(* Logix 5000 project; controller Test vendor 1 type 14 code 92 rev 33.11; software revision 33.03 *)

TASK MainTask (continuous, watchdog 500 ms) : MainProgram

MODULES
   Local : vendor 1 type 14 code 92 (ICP 0, rev 33.11)
      IN : vendor 1 type 7 code 1 (ICP 3, rev 3.2, Input RPI 20 ms)
      O : vendor 1 type 7 code 15 (ICP 2, rev 3.2, Output RPI 20 ms)
      Ethernet : 1756-ENBT (ICP 1, Ethernet 192.168.0.98, rev 6.4)
         IOLM1 : DXM (Ethernet 192.168.0.1, rev 2.22, StandardDataDriven RPI 20 ms)
              IOLM1:I.Data[184].0   // Output State
              IOLM1:I.Data[184].1   // Health Alarm State
END_MODULES

TYPE Banner_B25_Configuration_v4 :
STRUCT
   Sensor_Lockout : SINT;   // 0=Unlocked, 1=Locked
   Sensitivity : SINT;   // 0=Low, 1=Standard, 2=High
   Pin2_Function : SINT;   // 0=Disabled, 1=Remote Teach, 2=Detection Output, 3=Complementary Output, 4=NC Health, 5=NO Health
   Pin2_Pin4_Polarity : SINT;   // 0=NPN, 1=PNP, 2=Push Pull
   Output_Logic : SINT;   // 0=LO, 1= DO
   Output_Delay_Mode : SINT;   // 0=No Delay, 1=On/Off Delay
   Output_On_Delay : DINT;
   Output_Off_Delay : DINT;
   Dynamic_Teach_Timeout_Mode : SINT;   // 0=Cancel Teach, 1=Stop Teach
   Dynamic_Teach_Timeout_Duration : DINT;
   Health_Alarm_Threshold : SINT;
   Display_Disable : SINT;   // 0=Enabled, 1=Disabled
END_STRUCT
END_TYPE

TYPE Banner_B25_PDI_v4 :   // Process Data for a B25. This will include event information.
STRUCT
   Output_State : SINT;   // 0 = Inactive, 1 = Active
   Marginal_Signal : SINT;   // 0 = Normal, 1 = Marginal
END_STRUCT
END_TYPE

TYPE Banner_B25_RD_v4 :   // UDT that stores the Read Data for a B25.
STRUCT
   Direct : Banner_Direct_Parameters_v4;
   Serial_Number : STRING;
   Teach_State : SINT;   // 0=Idle, 1=SP1 Success, 2=SP2 Succes, 3=SP1 SP2 Success, 4 = Wait for Command, 5 = Busy, 7 = Error.
   Status : Banner_B25_Status_v4;
   All_Time_Run_Time_Counter : DINT;   // 0 to 2 Billion. 1/4 hr increments.
END_STRUCT
END_TYPE

TYPE Banner_B25_Status_v4 :
STRUCT
   Output_State : SINT;   // 0=Inactive, 1=Active
   Signal_Level : SINT;   // Signal Level - Switchpoit is at 50%, Taught Signal is at 100%
   Temperature : DINT;   // Internal Temperature
   Last_Taught_Temperature : DINT;   // Internal Temperature the last time device was taught
   Quality_of_Teach : SINT;   // 0=Not Taught, 1=Good, 2=Bad
   Health_Alarm_State : SINT;   // 0=No Alarm, 1= Alarm
   Quality_of_Health : INT;
END_STRUCT
END_TYPE

TYPE Banner_B25_v4 :   // All of the parameters for a B25.
STRUCT
   Initial_Global_Read : BOOL;   // Determines if all of the IO-Link data has been read into the PLC yet
   Command : INT;   // Value placed in here will activate a read or write to a specifc IO-Link Index
   Read : Banner_B25_RD_v4;   // Read Only Data
   Write : Banner_B25_WD_v4;   // Write Data
   Reset : BOOL;   // Resets AOI. This will force a complete parameter read of the sensor.
END_STRUCT
END_TYPE

TYPE Banner_B25_WD_v4 :   // UDT that stores the Write Data for a B25.
STRUCT
   System_Command : INT;   // See IODD file for list of commands that can be activated via the System Command interface
   Parameter_Access_Lock : SINT;   // Write access to all parameters is prohibited while value is 1. Only this parameter can be adjusted when value is 1.
   Data_Storage_Lock : SINT;   // Automatic data storage is disabled when this value is equal to 1. Read access is not affected.
   Local_Parameterization_Lock : SINT;   // Parameterization via local control elements on device is disabled.
   Local_User_Interface_Lock : SINT;   // Operation of local user interface is disabled.
   Configuration : Banner_B25_Configuration_v4;
   Resettable_Run_Time_Counter : DINT;   // 0 to 2 Billion. 1/4 hr increments.
   All_Time_Run_Time_Event_Time : DINT;   // 0 to 2 Billion. 1/4 hr increments.
   Resettable_Run_Time_Event_Time_Counter : DINT;   // 0 to 2 Billion. 1/4 hr increments.
END_STRUCT
END_TYPE

TYPE Banner_Direct_Parameters_v4 :
STRUCT
   Master_Cycle_Time : INT;
   Min_Cycle_Time : INT;
   M_Sequence_Capability : INT;
   IO_Link_Version_ID : INT;
   Process_Data_Input_Length : INT;
   Process_Data_Output_Length : INT;
   Combined_Vendor_ID : DINT;   // IO-Link Vendor ID
   Vendor_ID1 : INT;
   Vendor_ID2 : INT;
   Combined_Device_ID : DINT;   // IO-Link Device ID
   Device_ID1 : INT;
   Device_ID2 : INT;
   Device_ID3 : INT;
END_STRUCT
END_TYPE

TYPE Banner_IOL_Port_v4 :   // UDT that has all of the data items necessary to communicate with a specific Port on a IO-Link Master
STRUCT
   Port_Controlled : INT;   // Each bit represents a port on an IO-Link Master. Set to 1 to tell AOI to control that port.
   Port_Activate : INT;   // Each bit represents a port on an IO-Link Master. When ON that port will process any commands in queue.
   Port_Read : INT;   // Each bit represents a port on an IO-Link Master. Used to determine when device AOI has requested a Read command.
   Port_Write : INT;   // Each bit represents a port on an IO-Link Master. Used to determine when device AOI has requested a Write command.
   Port_RW_Complete : INT;   // Each bit represents a port on an IO-Link Master. Tells device AOI that Read or Write request has been completed.
   Port_Device_Read : INT;
   Data_Transfer : SINT[190];   // Array to transfer data from IO-Master to device AOIs.
END_STRUCT
END_TYPE

TYPE Banner_IOLM_EL_v4 :   // Error Log for Messages to IOLM.
STRUCT
   RW : SINT;   // 0 = Read, 1 = Write.
   Port : SINT;   // Port number that generated error.
   Index : INT;   // IO-Link Index for generated error.
END_STRUCT
END_TYPE

TYPE Banner_IOLM_v4 :   // UDT to control IO-Link Masters.
STRUCT
   Message_Source_Data : SINT[190];
   Message_Destination_Data : SINT[190];
   Error_Log : Banner_IOLM_EL_v4[10];
   Error_Write_Retry : BOOL;
   Num_Error_MSGS : DINT;
   IO_Link_Master_Busy : BOOL;   // 0 = While waiting for a command, 1 = Processing command
   AOI_Reset : BOOL;
   Port_Data : Banner_IOL_Port_v4;   // All of the necessary data to work with the various ports of the IO-Link Master.
   Halt_Operation : BOOL;   // When parameter is 1 the AOI is halted as next available time frame.
   AOI_Halted : BOOL;   // AOI is in standby mode until Halt Operation tag is set back to 0.
END_STRUCT
END_TYPE

ADD_ON_INSTRUCTION Banner_B25_Param_v4   (* revision 4.0, vendor Banner Engineering *)
// AOI to read and write parameter data to an IO-Link B25.
VAR_IN_OUT
   B25 : Banner_B25_v4; {required}
   Port_Data : Banner_IOL_Port_v4; {required}
END_VAR
VAR_INPUT
   Port : DINT; {required}
END_VAR
VAR
   Local_Control : DINT; {access None}
   Global_Read_Command_Value : INT; {access None}
   Global_Write_Command_Value : INT; {access None}
   Command_Being_Processed : BOOL; {access None}
   Update_Archive : BOOL; {access None}
   Index_Write_Inprocess : INT; {access None}
   Index_Write_Control : INT; {access None}
   Inprocess_Index : DINT; {access None}
END_VAR

ROUTINE Logic   (* ladder *)
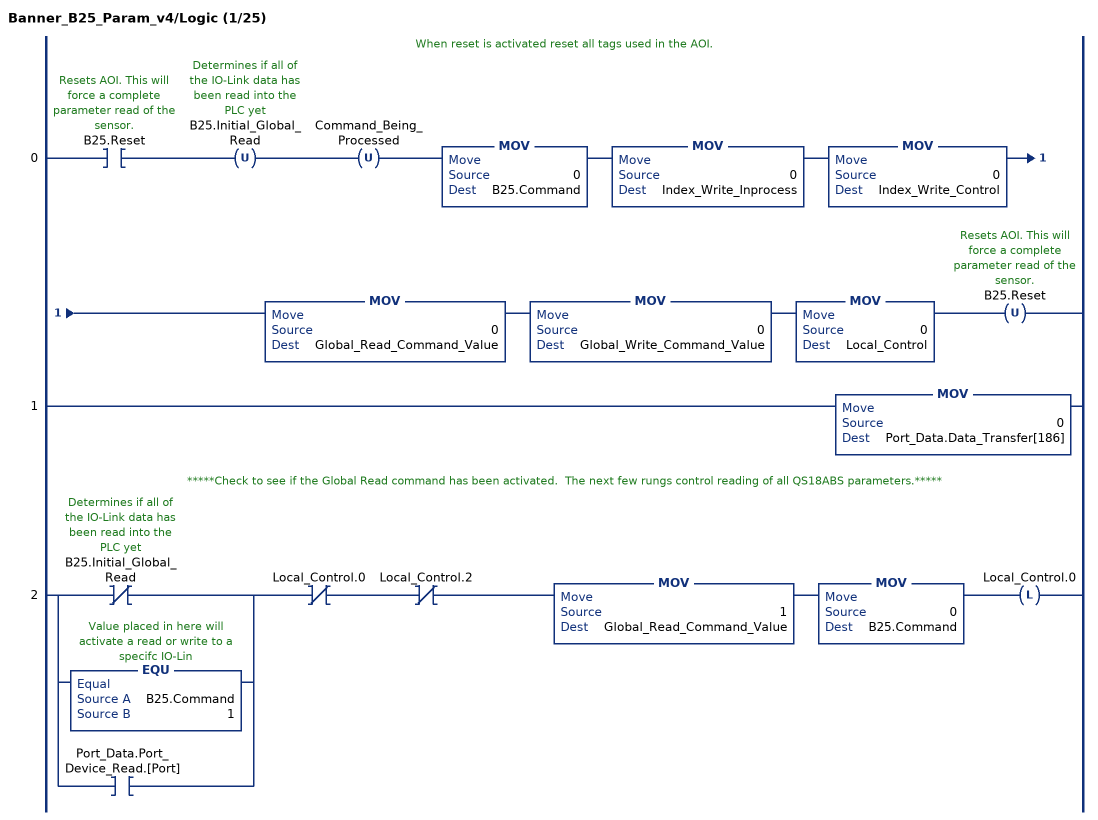
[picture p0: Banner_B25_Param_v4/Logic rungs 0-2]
   // When reset is activated reset all tags used in the AOI.
   0: XIC(B25.Reset)OTU(B25.Initial_Global_Read)OTU(Command_Being_Processed)MOV(0,B25.Command)MOV(0,Index_Write_Inprocess)MOV(0,Index_Write_Control)MOV(0,Global_Read_Command_Value)MOV(0,Global_Write_Command_Value)MOV(0,Local_Control)OTU(B25.Reset);
   1: MOV(0,Port_Data.Data_Transfer[186]);
   // *****Check to see if the Global Read command has been activated.  The next few rungs control reading of all QS18ABS parameters.*****
   2: [XIO(B25.Initial_Global_Read) ,EQU(B25.Command,1) ,XIC(Port_Data.Port_Device_Read.[Port]) ]XIO(Local_Control.0)XIO(Local_Control.2)MOV(1,Global_Read_Command_Value)MOV(0,B25.Command)OTL(Local_Control.0);
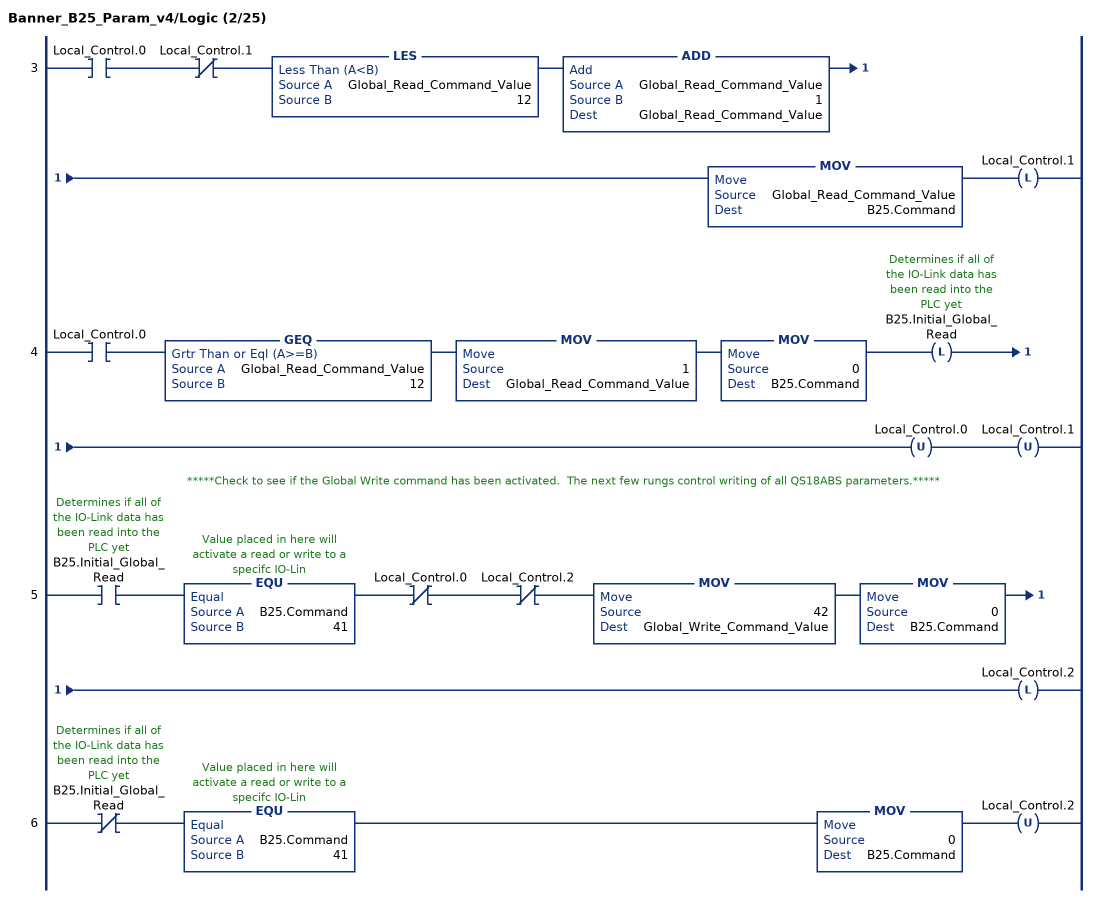
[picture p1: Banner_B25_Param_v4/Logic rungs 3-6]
   3: XIC(Local_Control.0)XIO(Local_Control.1)LES(Global_Read_Command_Value,12)ADD(Global_Read_Command_Value,1,Global_Read_Command_Value)MOV(Global_Read_Command_Value,B25.Command)OTL(Local_Control.1);
   4: XIC(Local_Control.0)GEQ(Global_Read_Command_Value,12)MOV(1,Global_Read_Command_Value)MOV(0,B25.Command)OTL(B25.Initial_Global_Read)OTU(Local_Control.0)OTU(Local_Control.1);
   // *****Check to see if the Global Write command has been activated.  The next few rungs control writing of all QS18ABS parameters.*****
   5: XIC(B25.Initial_Global_Read)EQU(B25.Command,41)XIO(Local_Control.0)XIO(Local_Control.2)MOV(42,Global_Write_Command_Value)MOV(0,B25.Command)OTL(Local_Control.2);
   6: XIO(B25.Initial_Global_Read)EQU(B25.Command,41)MOV(0,B25.Command)OTU(Local_Control.2);
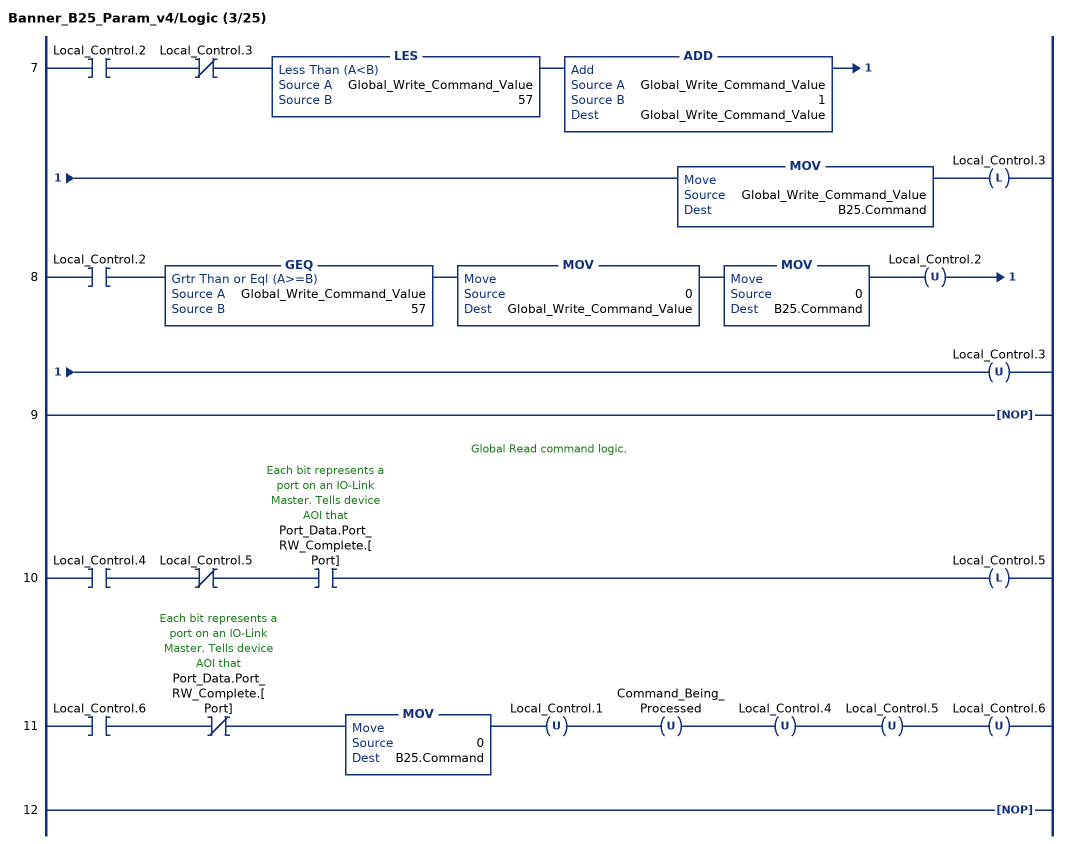
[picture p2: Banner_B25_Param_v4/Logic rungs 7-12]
   7: XIC(Local_Control.2)XIO(Local_Control.3)LES(Global_Write_Command_Value,57)ADD(Global_Write_Command_Value,1,Global_Write_Command_Value)MOV(Global_Write_Command_Value,B25.Command)OTL(Local_Control.3);
   8: XIC(Local_Control.2)GEQ(Global_Write_Command_Value,57)MOV(0,Global_Write_Command_Value)MOV(0,B25.Command)OTU(Local_Control.2)OTU(Local_Control.3);
   9: NOP();
   // Global Read command logic.
   10: XIC(Local_Control.4)XIO(Local_Control.5)XIC(Port_Data.Port_RW_Complete.[Port])OTL(Local_Control.5);
   11: XIC(Local_Control.6)XIO(Port_Data.Port_RW_Complete.[Port])MOV(0,B25.Command)OTU(Local_Control.1)OTU(Command_Being_Processed)OTU(Local_Control.4)OTU(Local_Control.5)OTU(Local_Control.6);
   12: NOP();
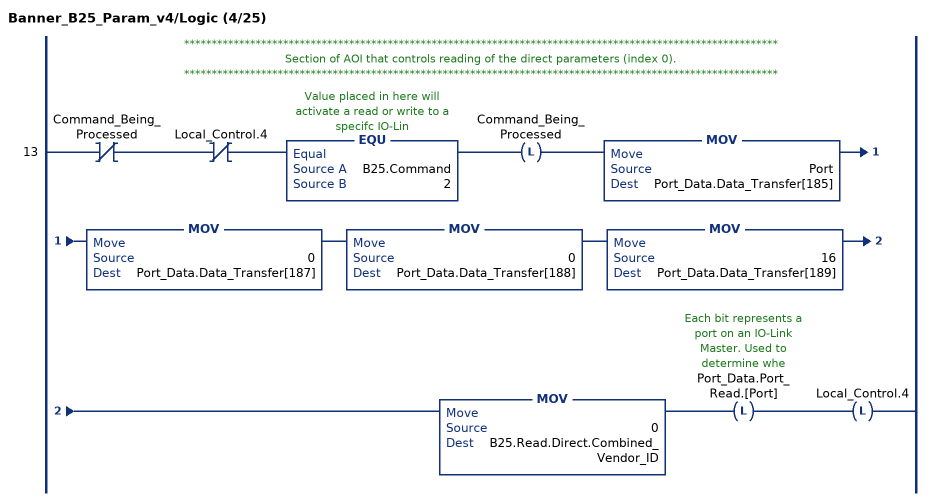
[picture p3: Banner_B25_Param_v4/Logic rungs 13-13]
   // ************************************************************************************************************
   // Section of AOI that controls reading of the direct parameters (index 0).
   // ************************************************************************************************************
   13: XIO(Command_Being_Processed)XIO(Local_Control.4)EQU(B25.Command,2)OTL(Command_Being_Processed)MOV(Port,Port_Data.Data_Transfer[185])MOV(0,Port_Data.Data_Transfer[187])MOV(0,Port_Data.Data_Transfer[188])MOV(16,Port_Data.Data_Transfer[189])MOV(0,B25.Read.Direct.Combined_Vendor_ID)OTL(Port_Data.Port_Read.[Port])OTL(Local_Control.4);
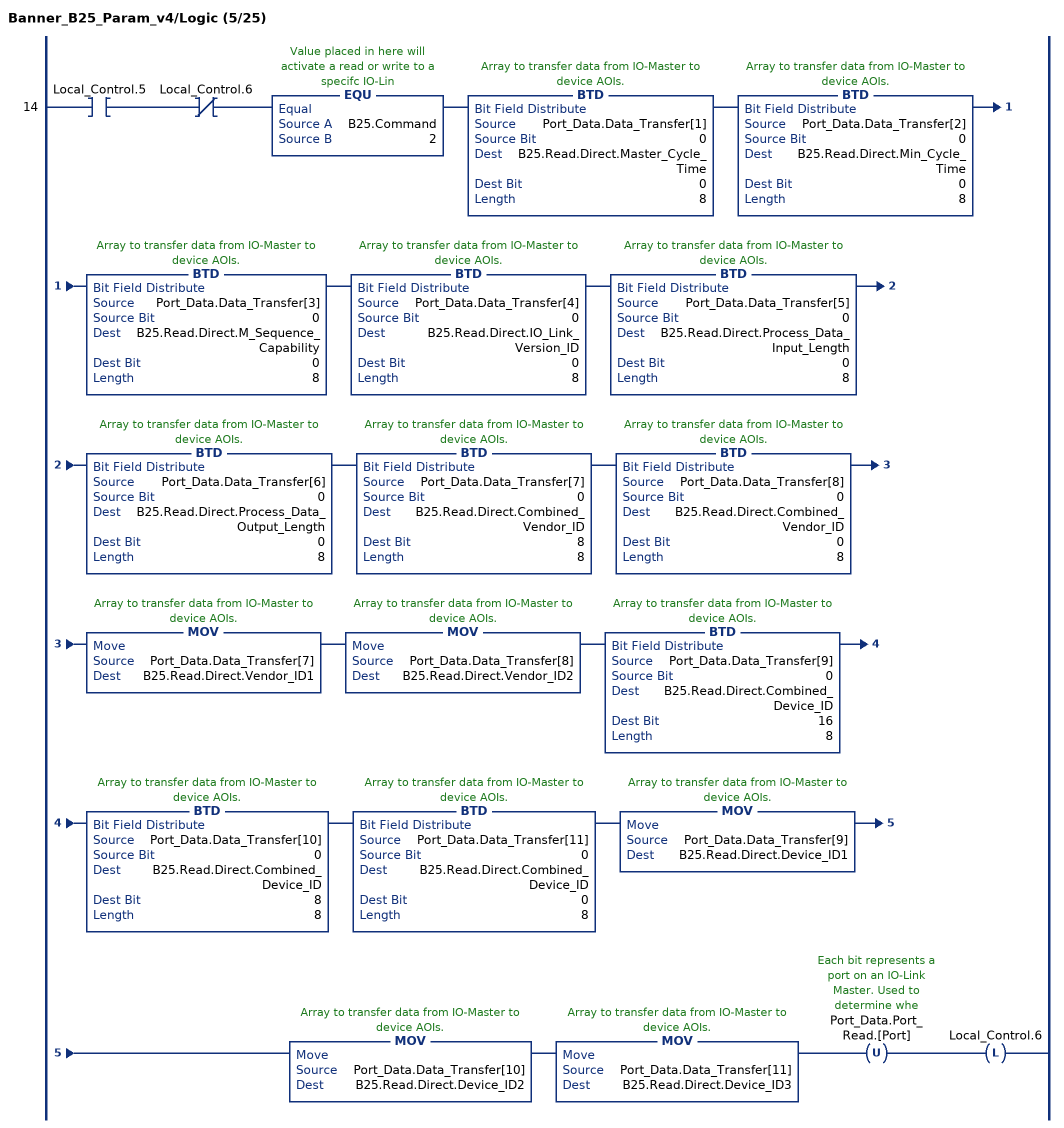
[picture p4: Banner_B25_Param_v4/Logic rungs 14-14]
   14: XIC(Local_Control.5)XIO(Local_Control.6)EQU(B25.Command,2)BTD(Port_Data.Data_Transfer[1],0,B25.Read.Direct.Master_Cycle_Time,0,8)BTD(Port_Data.Data_Transfer[2],0,B25.Read.Direct.Min_Cycle_Time,0,8)BTD(Port_Data.Data_Transfer[3],0,B25.Read.Direct.M_Sequence_Capability,0,8)BTD(Port_Data.Data_Transfer[4],0,B25.Read.Direct.IO_Link_Version_ID,0,8)BTD(Port_Data.Data_Transfer[5],0,B25.Read.Direct.Process_Data_Input_Length,0,8)BTD(Port_Data.Data_Transfer[6],0,B25.Read.Direct.Process_Data_Output_Length,0,8)BTD(Port_Data.Data_Transfer[7],0,B25.Read.Direct.Combined_Vendor_ID,8,8)BTD(Port_Data.Data_Transfer[8],0,B25.Read.Direct.Combined_Vendor_ID,0,8)MOV(Port_Data.Data_Transfer[7],B25.Read.Direct.Vendor_ID1)MOV(Port_Data.Data_Transfer[8],B25.Read.Direct.Vendor_ID2)BTD(Port_Data.Data_Transfer[9],0,B25.Read.Direct.Combined_Device_ID,16,8)BTD(Port_Data.Data_Transfer[10],0,B25.Read.Direct.Combined_Device_ID,8,8)BTD(Port_Data.Data_Transfer[11],0,B25.Read.Direct.Combined_Device_ID,0,8)MOV(Port_Data.Data_Transfer[9],B25.Read.Direct.Device_ID1)MOV(Port_Data.Data_Transfer[10],B25.Read.Direct.Device_ID2)MOV(Port_Data.Data_Transfer[11],B25.Read.Direct.Device_ID3)OTU(Port_Data.Port_Read.[Port])OTL(Local_Control.6);
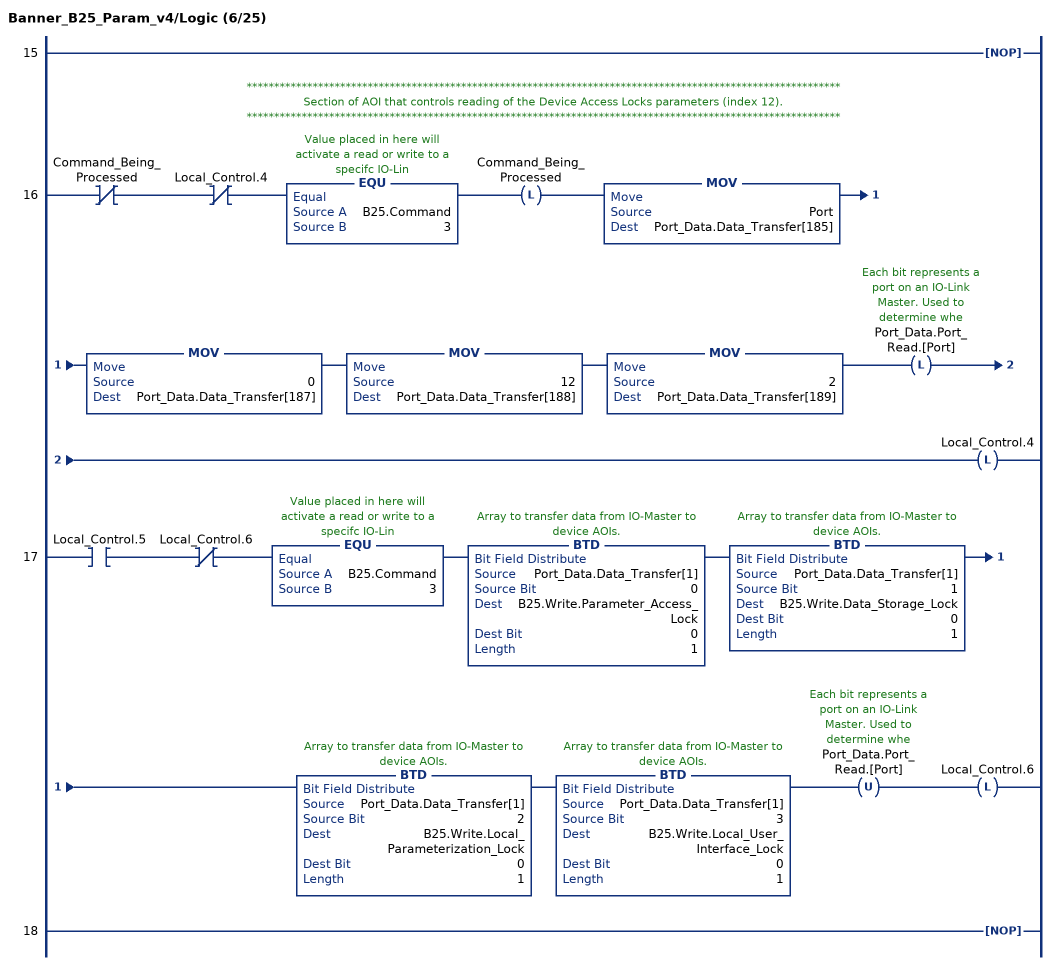
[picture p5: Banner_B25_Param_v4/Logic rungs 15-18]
   15: NOP();
   // ************************************************************************************************************
   // Section of AOI that controls reading of the Device Access Locks parameters (index 12).
   // ************************************************************************************************************
   16: XIO(Command_Being_Processed)XIO(Local_Control.4)EQU(B25.Command,3)OTL(Command_Being_Processed)MOV(Port,Port_Data.Data_Transfer[185])MOV(0,Port_Data.Data_Transfer[187])MOV(12,Port_Data.Data_Transfer[188])MOV(2,Port_Data.Data_Transfer[189])OTL(Port_Data.Port_Read.[Port])OTL(Local_Control.4);
   17: XIC(Local_Control.5)XIO(Local_Control.6)EQU(B25.Command,3)BTD(Port_Data.Data_Transfer[1],0,B25.Write.Parameter_Access_Lock,0,1)BTD(Port_Data.Data_Transfer[1],1,B25.Write.Data_Storage_Lock,0,1)BTD(Port_Data.Data_Transfer[1],2,B25.Write.Local_Parameterization_Lock,0,1)BTD(Port_Data.Data_Transfer[1],3,B25.Write.Local_User_Interface_Lock,0,1)OTU(Port_Data.Port_Read.[Port])OTL(Local_Control.6);
   18: NOP();
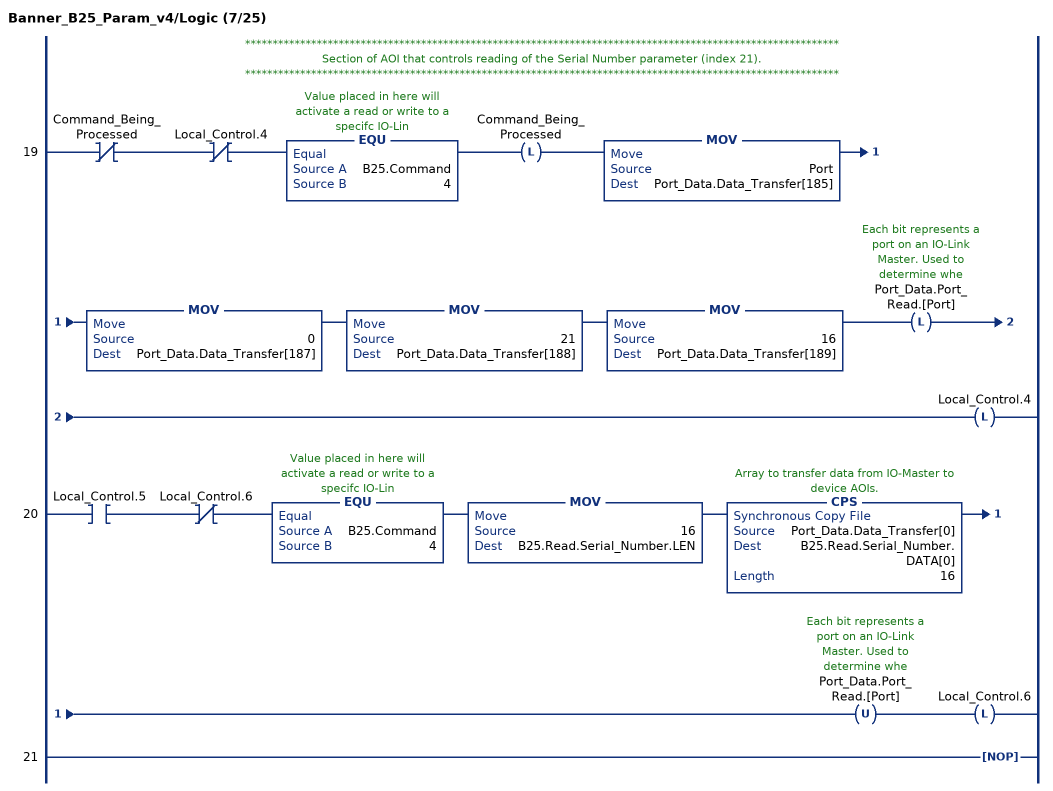
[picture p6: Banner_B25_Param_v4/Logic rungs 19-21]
   // ************************************************************************************************************
   // Section of AOI that controls reading of the Serial Number parameter (index 21).
   // ************************************************************************************************************
   19: XIO(Command_Being_Processed)XIO(Local_Control.4)EQU(B25.Command,4)OTL(Command_Being_Processed)MOV(Port,Port_Data.Data_Transfer[185])MOV(0,Port_Data.Data_Transfer[187])MOV(21,Port_Data.Data_Transfer[188])MOV(16,Port_Data.Data_Transfer[189])OTL(Port_Data.Port_Read.[Port])OTL(Local_Control.4);
   20: XIC(Local_Control.5)XIO(Local_Control.6)EQU(B25.Command,4)MOV(16,B25.Read.Serial_Number.LEN)CPS(Port_Data.Data_Transfer[0],B25.Read.Serial_Number.DATA[0],16)OTU(Port_Data.Port_Read.[Port])OTL(Local_Control.6);
   21: NOP();
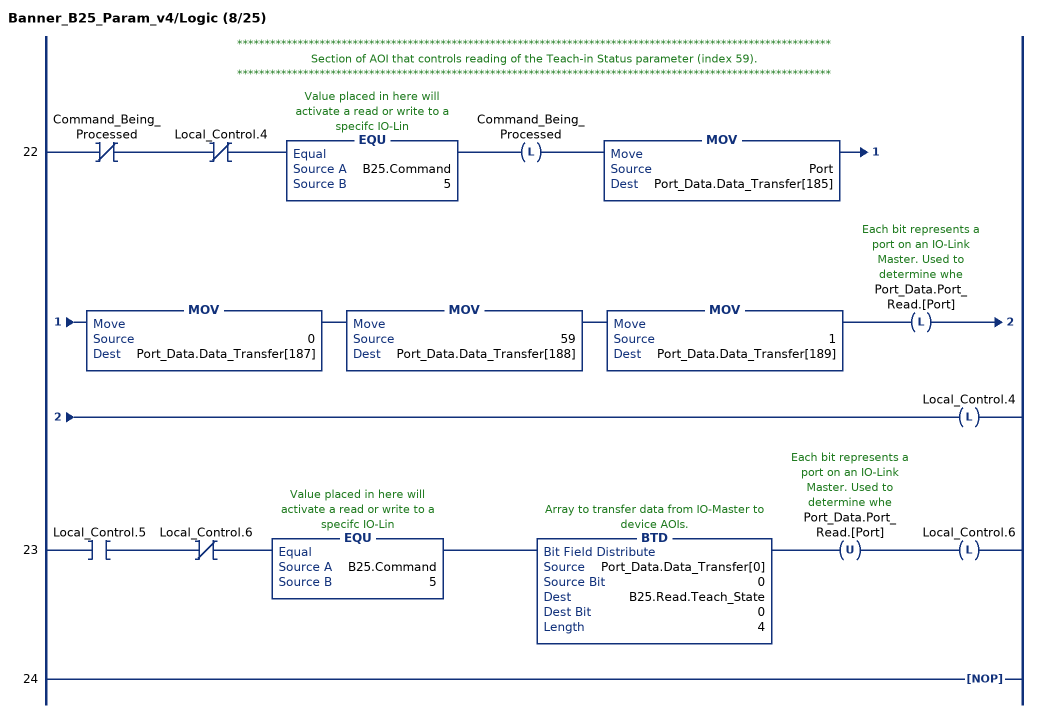
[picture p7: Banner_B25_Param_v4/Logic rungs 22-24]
   // ************************************************************************************************************
   // Section of AOI that controls reading of the Teach-in Status parameter (index 59).
   // ************************************************************************************************************
   22: XIO(Command_Being_Processed)XIO(Local_Control.4)EQU(B25.Command,5)OTL(Command_Being_Processed)MOV(Port,Port_Data.Data_Transfer[185])MOV(0,Port_Data.Data_Transfer[187])MOV(59,Port_Data.Data_Transfer[188])MOV(1,Port_Data.Data_Transfer[189])OTL(Port_Data.Port_Read.[Port])OTL(Local_Control.4);
   23: XIC(Local_Control.5)XIO(Local_Control.6)EQU(B25.Command,5)BTD(Port_Data.Data_Transfer[0],0,B25.Read.Teach_State,0,4)OTU(Port_Data.Port_Read.[Port])OTL(Local_Control.6);
   24: NOP();
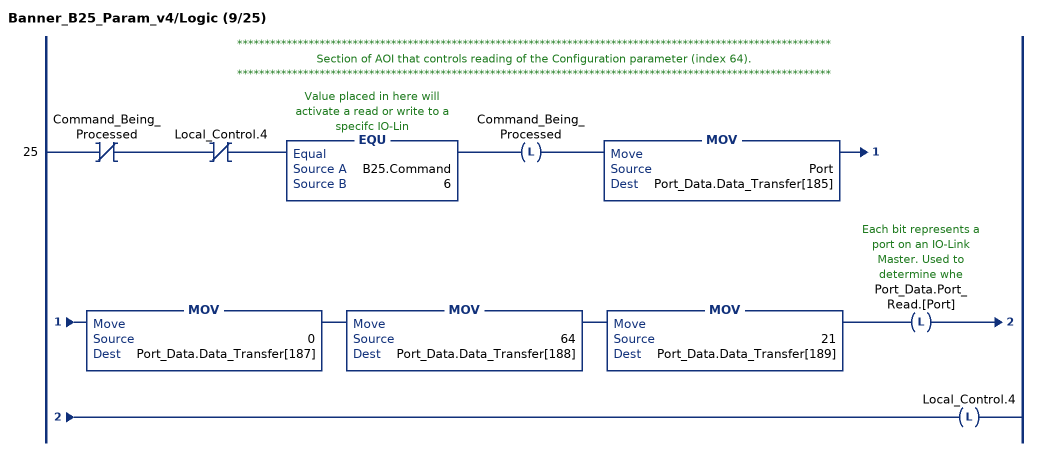
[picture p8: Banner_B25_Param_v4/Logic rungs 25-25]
   // ************************************************************************************************************
   // Section of AOI that controls reading of the Configuration parameter (index 64).
   // ************************************************************************************************************
   25: XIO(Command_Being_Processed)XIO(Local_Control.4)EQU(B25.Command,6)OTL(Command_Being_Processed)MOV(Port,Port_Data.Data_Transfer[185])MOV(0,Port_Data.Data_Transfer[187])MOV(64,Port_Data.Data_Transfer[188])MOV(21,Port_Data.Data_Transfer[189])OTL(Port_Data.Port_Read.[Port])OTL(Local_Control.4);
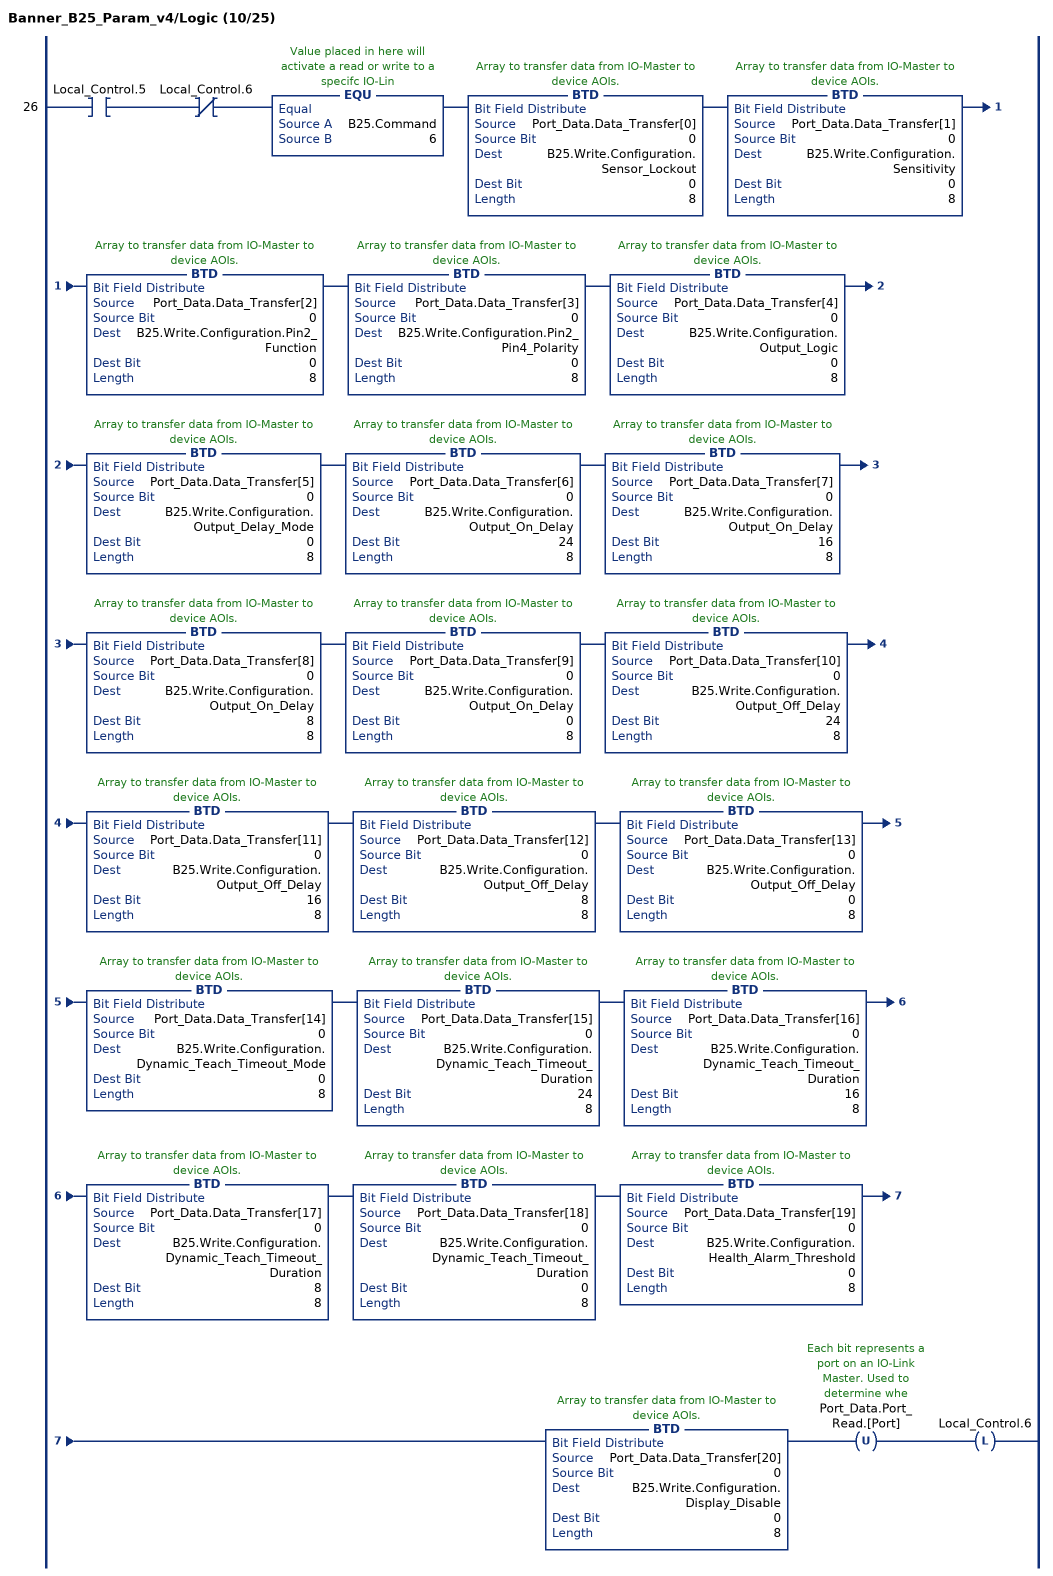
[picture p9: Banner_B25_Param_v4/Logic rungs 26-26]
   26: XIC(Local_Control.5)XIO(Local_Control.6)EQU(B25.Command,6)BTD(Port_Data.Data_Transfer[0],0,B25.Write.Configuration.Sensor_Lockout,0,8)BTD(Port_Data.Data_Transfer[1],0,B25.Write.Configuration.Sensitivity,0,8)BTD(Port_Data.Data_Transfer[2],0,B25.Write.Configuration.Pin2_Function,0,8)BTD(Port_Data.Data_Transfer[3],0,B25.Write.Configuration.Pin2_Pin4_Polarity,0,8)BTD(Port_Data.Data_Transfer[4],0,B25.Write.Configuration.Output_Logic,0,8)BTD(Port_Data.Data_Transfer[5],0,B25.Write.Configuration.Output_Delay_Mode,0,8)BTD(Port_Data.Data_Transfer[6],0,B25.Write.Configuration.Output_On_Delay,24,8)BTD(Port_Data.Data_Transfer[7],0,B25.Write.Configuration.Output_On_Delay,16,8)BTD(Port_Data.Data_Transfer[8],0,B25.Write.Configuration.Output_On_Delay,8,8)BTD(Port_Data.Data_Transfer[9],0,B25.Write.Configuration.Output_On_Delay,0,8)BTD(Port_Data.Data_Transfer[10],0,B25.Write.Configuration.Output_Off_Delay,24,8)BTD(Port_Data.Data_Transfer[11],0,B25.Write.Configuration.Output_Off_Delay,16,8)BTD(Port_Data.Data_Transfer[12],0,B25.Write.Configuration.Output_Off_Delay,8,8)BTD(Port_Data.Data_Transfer[13],0,B25.Write.Configuration.Output_Off_Delay,0,8)BTD(Port_Data.Data_Transfer[14],0,B25.Write.Configuration.Dynamic_Teach_Timeout_Mode,0,8)BTD(Port_Data.Data_Transfer[15],0,B25.Write.Configuration.Dynamic_Teach_Timeout_Duration,24,8)BTD(Port_Data.Data_Transfer[16],0,B25.Write.Configuration.Dynamic_Teach_Timeout_Duration,16,8)BTD(Port_Data.Data_Transfer[17],0,B25.Write.Configuration.Dynamic_Teach_Timeout_Duration,8,8)BTD(Port_Data.Data_Transfer[18],0,B25.Write.Configuration.Dynamic_Teach_Timeout_Duration,0,8)BTD(Port_Data.Data_Transfer[19],0,B25.Write.Configuration.Health_Alarm_Threshold,0,8)BTD(Port_Data.Data_Transfer[20],0,B25.Write.Configuration.Display_Disable,0,8)OTU(Port_Data.Port_Read.[Port])OTL(Local_Control.6);
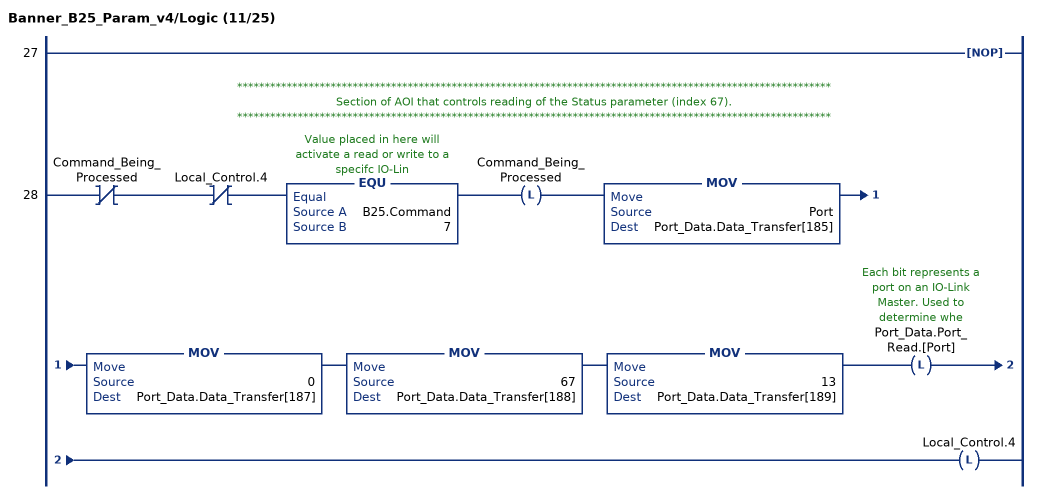
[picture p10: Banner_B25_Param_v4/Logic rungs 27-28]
   27: NOP();
   // ************************************************************************************************************
   // Section of AOI that controls reading of the Status parameter (index 67).
   // ************************************************************************************************************
   28: XIO(Command_Being_Processed)XIO(Local_Control.4)EQU(B25.Command,7)OTL(Command_Being_Processed)MOV(Port,Port_Data.Data_Transfer[185])MOV(0,Port_Data.Data_Transfer[187])MOV(67,Port_Data.Data_Transfer[188])MOV(13,Port_Data.Data_Transfer[189])OTL(Port_Data.Port_Read.[Port])OTL(Local_Control.4);
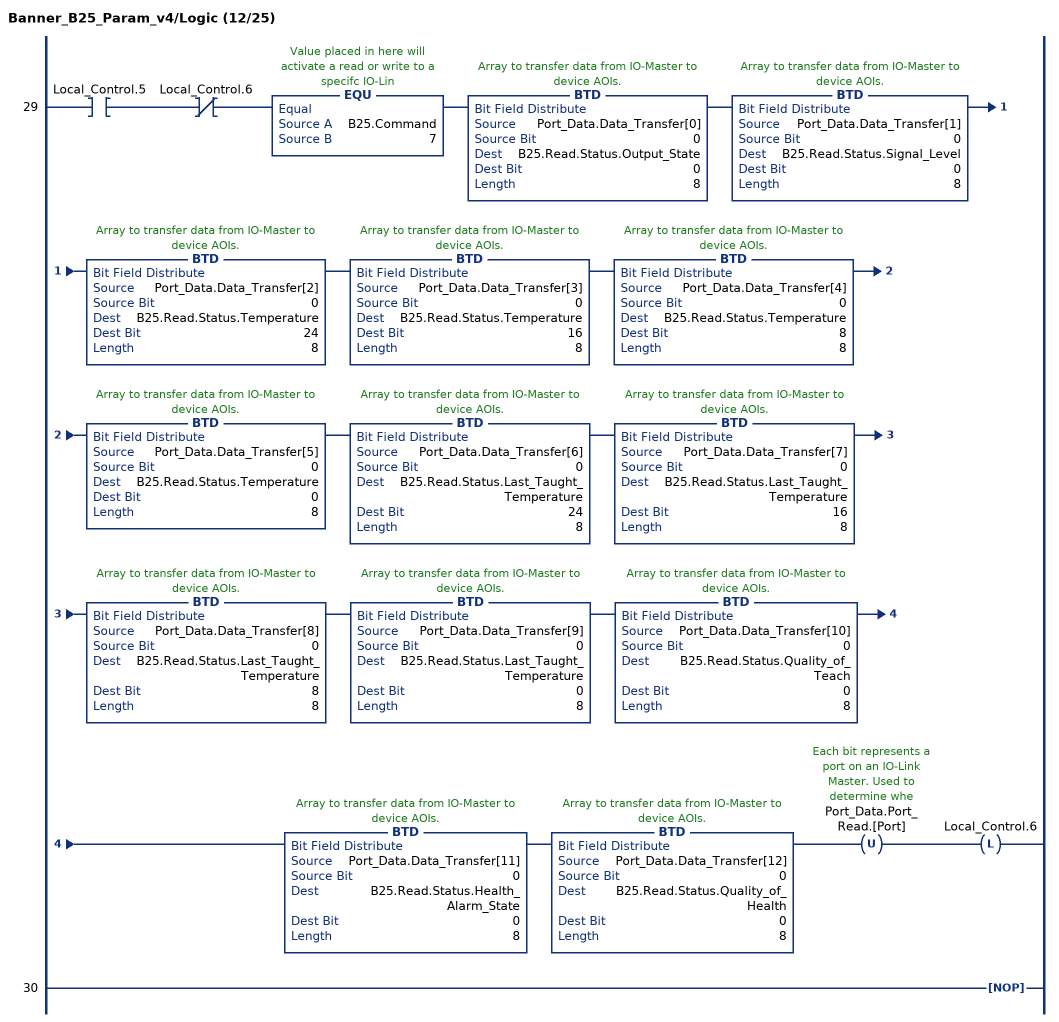
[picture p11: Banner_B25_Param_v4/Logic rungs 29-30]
   29: XIC(Local_Control.5)XIO(Local_Control.6)EQU(B25.Command,7)BTD(Port_Data.Data_Transfer[0],0,B25.Read.Status.Output_State,0,8)BTD(Port_Data.Data_Transfer[1],0,B25.Read.Status.Signal_Level,0,8)BTD(Port_Data.Data_Transfer[2],0,B25.Read.Status.Temperature,24,8)BTD(Port_Data.Data_Transfer[3],0,B25.Read.Status.Temperature,16,8)BTD(Port_Data.Data_Transfer[4],0,B25.Read.Status.Temperature,8,8)BTD(Port_Data.Data_Transfer[5],0,B25.Read.Status.Temperature,0,8)BTD(Port_Data.Data_Transfer[6],0,B25.Read.Status.Last_Taught_Temperature,24,8)BTD(Port_Data.Data_Transfer[7],0,B25.Read.Status.Last_Taught_Temperature,16,8)BTD(Port_Data.Data_Transfer[8],0,B25.Read.Status.Last_Taught_Temperature,8,8)BTD(Port_Data.Data_Transfer[9],0,B25.Read.Status.Last_Taught_Temperature,0,8)BTD(Port_Data.Data_Transfer[10],0,B25.Read.Status.Quality_of_Teach,0,8)BTD(Port_Data.Data_Transfer[11],0,B25.Read.Status.Health_Alarm_State,0,8)BTD(Port_Data.Data_Transfer[12],0,B25.Read.Status.Quality_of_Health,0,8)OTU(Port_Data.Port_Read.[Port])OTL(Local_Control.6);
   30: NOP();
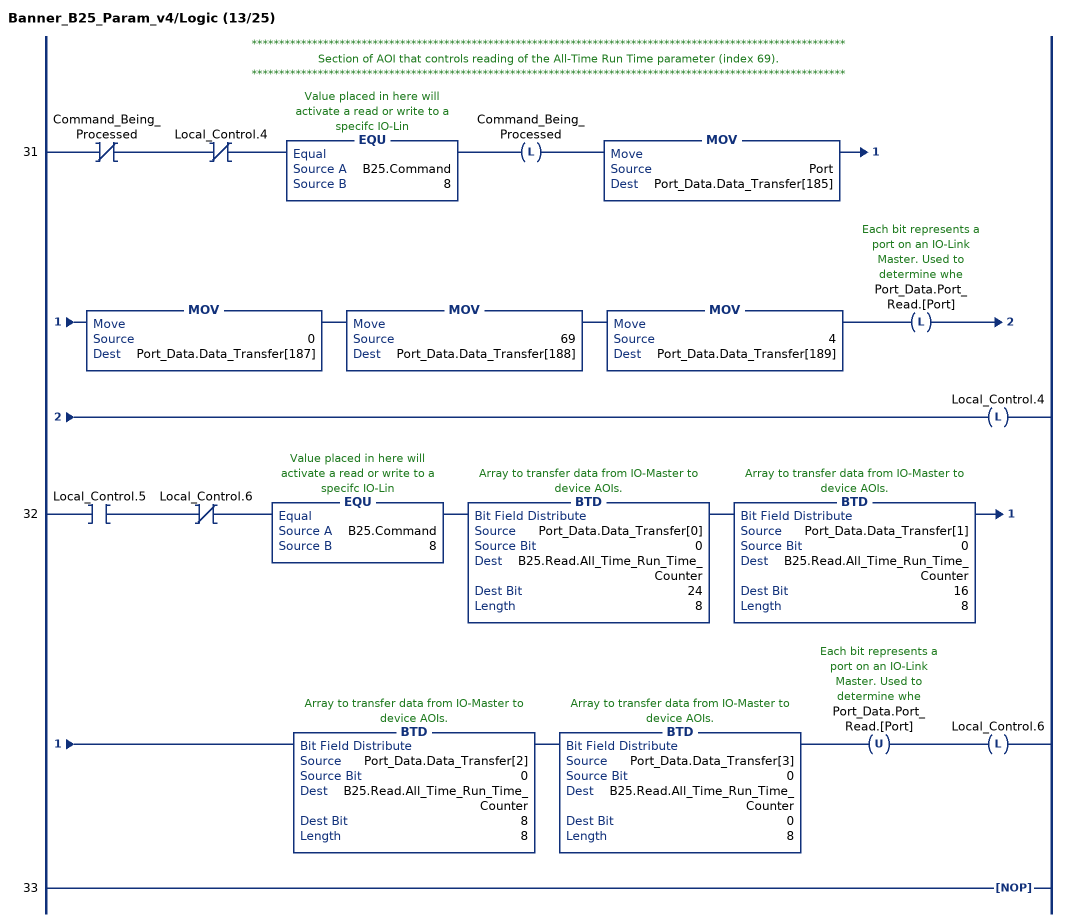
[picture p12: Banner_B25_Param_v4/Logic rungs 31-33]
   // ************************************************************************************************************
   // Section of AOI that controls reading of the All-Time Run Time parameter (index 69).
   // ************************************************************************************************************
   31: XIO(Command_Being_Processed)XIO(Local_Control.4)EQU(B25.Command,8)OTL(Command_Being_Processed)MOV(Port,Port_Data.Data_Transfer[185])MOV(0,Port_Data.Data_Transfer[187])MOV(69,Port_Data.Data_Transfer[188])MOV(4,Port_Data.Data_Transfer[189])OTL(Port_Data.Port_Read.[Port])OTL(Local_Control.4);
   32: XIC(Local_Control.5)XIO(Local_Control.6)EQU(B25.Command,8)BTD(Port_Data.Data_Transfer[0],0,B25.Read.All_Time_Run_Time_Counter,24,8)BTD(Port_Data.Data_Transfer[1],0,B25.Read.All_Time_Run_Time_Counter,16,8)BTD(Port_Data.Data_Transfer[2],0,B25.Read.All_Time_Run_Time_Counter,8,8)BTD(Port_Data.Data_Transfer[3],0,B25.Read.All_Time_Run_Time_Counter,0,8)OTU(Port_Data.Port_Read.[Port])OTL(Local_Control.6);
   33: NOP();
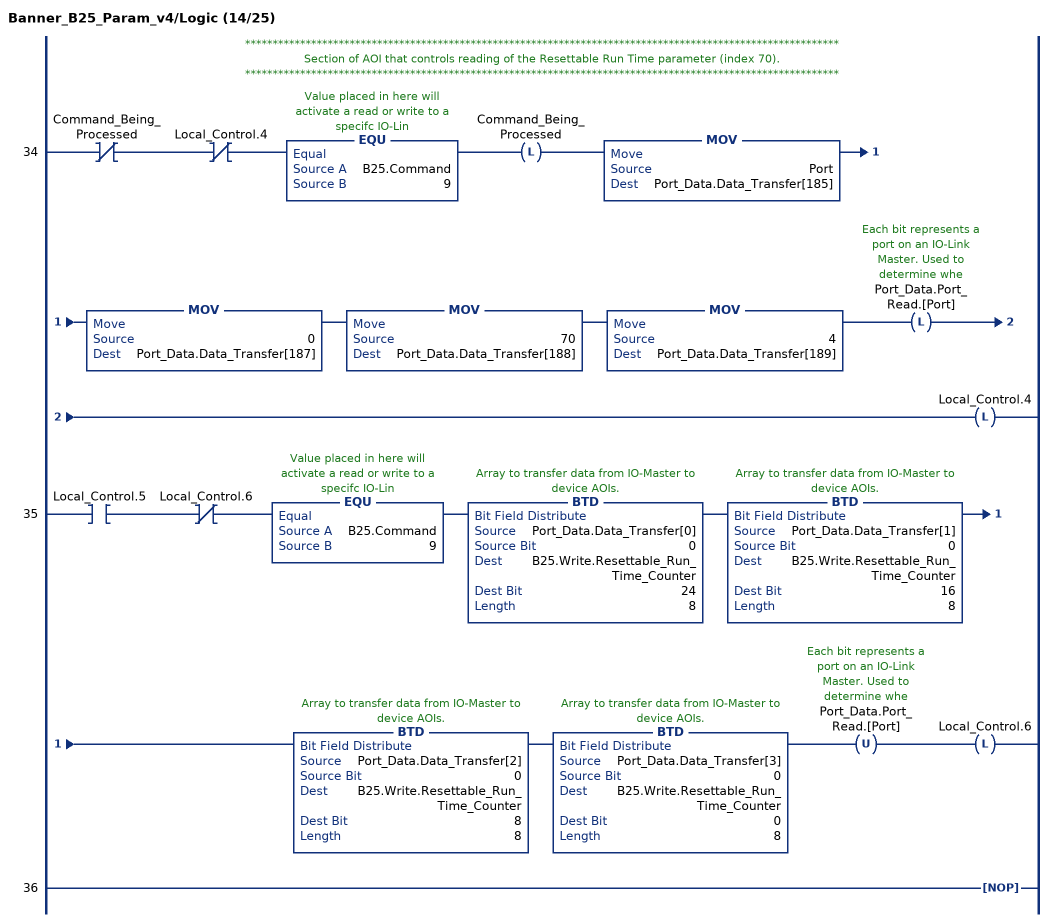
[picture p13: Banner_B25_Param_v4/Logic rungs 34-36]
   // ************************************************************************************************************
   // Section of AOI that controls reading of the Resettable Run Time parameter (index 70).
   // ************************************************************************************************************
   34: XIO(Command_Being_Processed)XIO(Local_Control.4)EQU(B25.Command,9)OTL(Command_Being_Processed)MOV(Port,Port_Data.Data_Transfer[185])MOV(0,Port_Data.Data_Transfer[187])MOV(70,Port_Data.Data_Transfer[188])MOV(4,Port_Data.Data_Transfer[189])OTL(Port_Data.Port_Read.[Port])OTL(Local_Control.4);
   35: XIC(Local_Control.5)XIO(Local_Control.6)EQU(B25.Command,9)BTD(Port_Data.Data_Transfer[0],0,B25.Write.Resettable_Run_Time_Counter,24,8)BTD(Port_Data.Data_Transfer[1],0,B25.Write.Resettable_Run_Time_Counter,16,8)BTD(Port_Data.Data_Transfer[2],0,B25.Write.Resettable_Run_Time_Counter,8,8)BTD(Port_Data.Data_Transfer[3],0,B25.Write.Resettable_Run_Time_Counter,0,8)OTU(Port_Data.Port_Read.[Port])OTL(Local_Control.6);
   36: NOP();
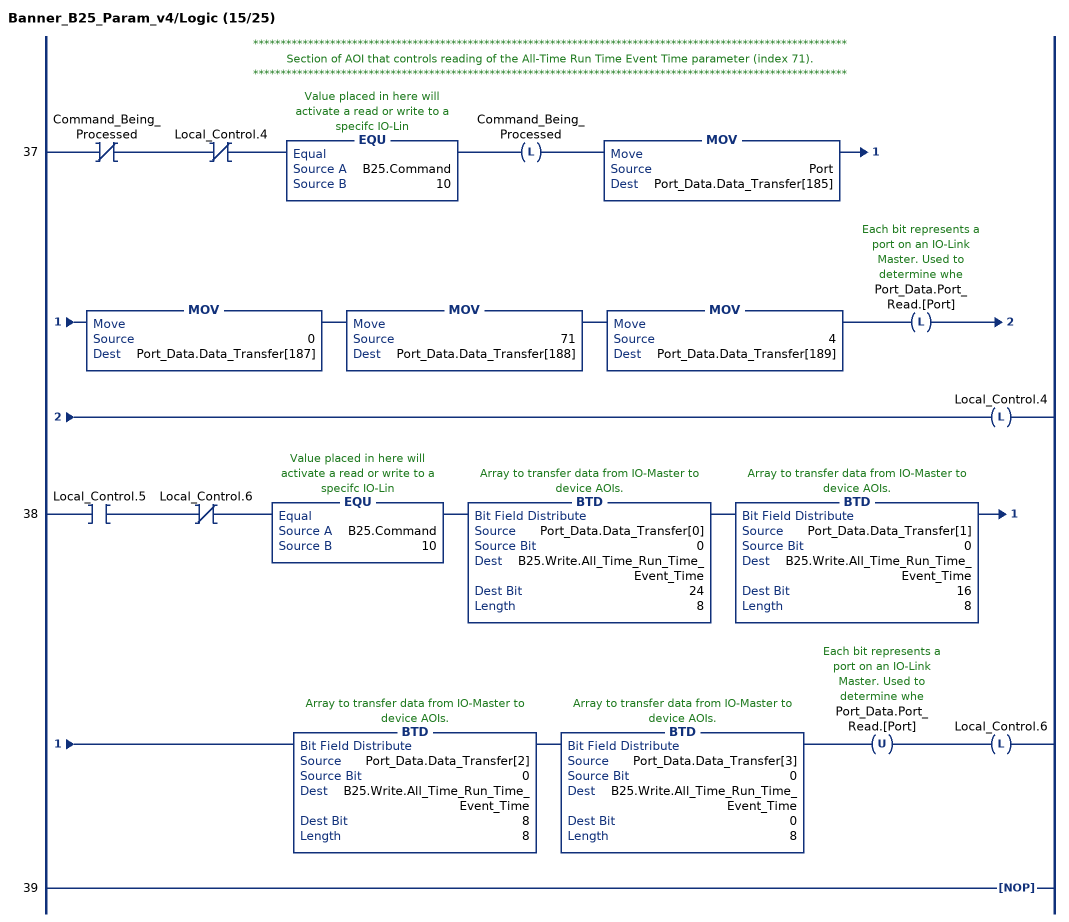
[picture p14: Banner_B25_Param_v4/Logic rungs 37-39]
   // ************************************************************************************************************
   // Section of AOI that controls reading of the All-Time Run Time Event Time parameter (index 71).
   // ************************************************************************************************************
   37: XIO(Command_Being_Processed)XIO(Local_Control.4)EQU(B25.Command,10)OTL(Command_Being_Processed)MOV(Port,Port_Data.Data_Transfer[185])MOV(0,Port_Data.Data_Transfer[187])MOV(71,Port_Data.Data_Transfer[188])MOV(4,Port_Data.Data_Transfer[189])OTL(Port_Data.Port_Read.[Port])OTL(Local_Control.4);
   38: XIC(Local_Control.5)XIO(Local_Control.6)EQU(B25.Command,10)BTD(Port_Data.Data_Transfer[0],0,B25.Write.All_Time_Run_Time_Event_Time,24,8)BTD(Port_Data.Data_Transfer[1],0,B25.Write.All_Time_Run_Time_Event_Time,16,8)BTD(Port_Data.Data_Transfer[2],0,B25.Write.All_Time_Run_Time_Event_Time,8,8)BTD(Port_Data.Data_Transfer[3],0,B25.Write.All_Time_Run_Time_Event_Time,0,8)OTU(Port_Data.Port_Read.[Port])OTL(Local_Control.6);
   39: NOP();
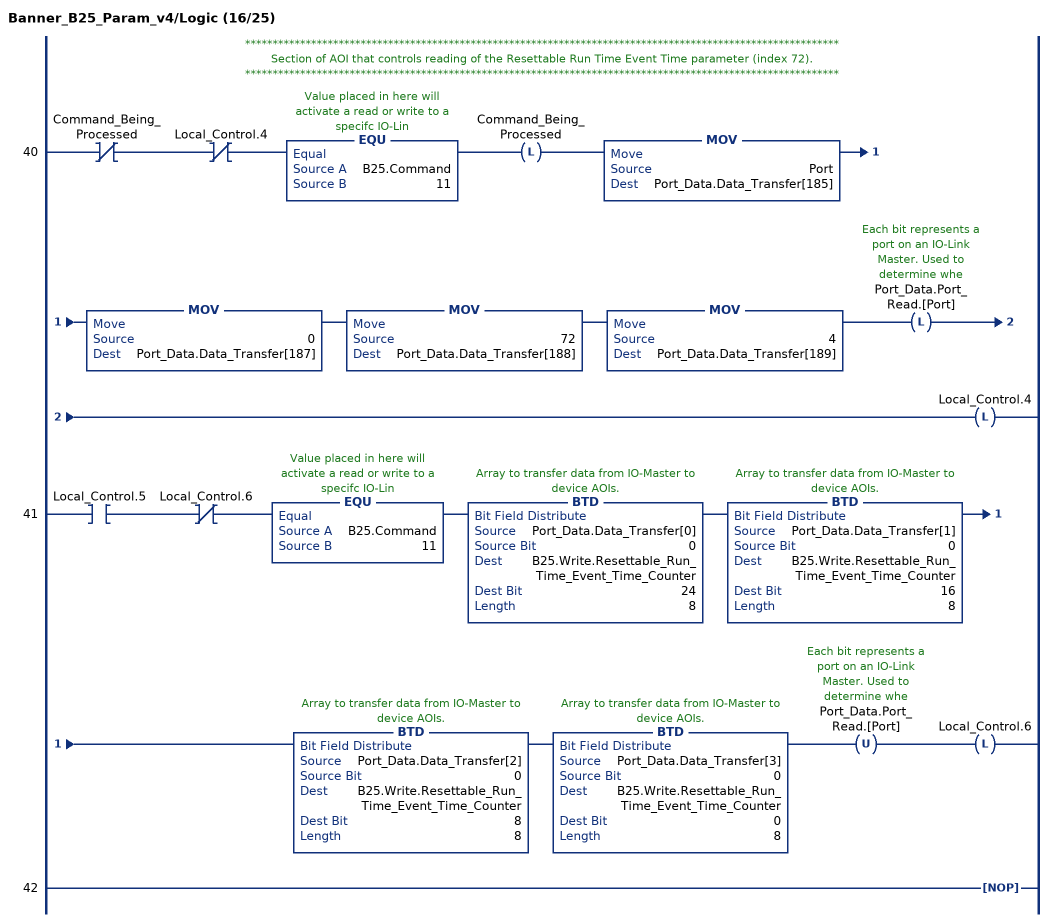
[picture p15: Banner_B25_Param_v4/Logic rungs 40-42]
   // ************************************************************************************************************
   // Section of AOI that controls reading of the Resettable Run Time Event Time parameter (index 72).
   // ************************************************************************************************************
   40: XIO(Command_Being_Processed)XIO(Local_Control.4)EQU(B25.Command,11)OTL(Command_Being_Processed)MOV(Port,Port_Data.Data_Transfer[185])MOV(0,Port_Data.Data_Transfer[187])MOV(72,Port_Data.Data_Transfer[188])MOV(4,Port_Data.Data_Transfer[189])OTL(Port_Data.Port_Read.[Port])OTL(Local_Control.4);
   41: XIC(Local_Control.5)XIO(Local_Control.6)EQU(B25.Command,11)BTD(Port_Data.Data_Transfer[0],0,B25.Write.Resettable_Run_Time_Event_Time_Counter,24,8)BTD(Port_Data.Data_Transfer[1],0,B25.Write.Resettable_Run_Time_Event_Time_Counter,16,8)BTD(Port_Data.Data_Transfer[2],0,B25.Write.Resettable_Run_Time_Event_Time_Counter,8,8)BTD(Port_Data.Data_Transfer[3],0,B25.Write.Resettable_Run_Time_Event_Time_Counter,0,8)OTU(Port_Data.Port_Read.[Port])OTL(Local_Control.6);
   42: NOP();
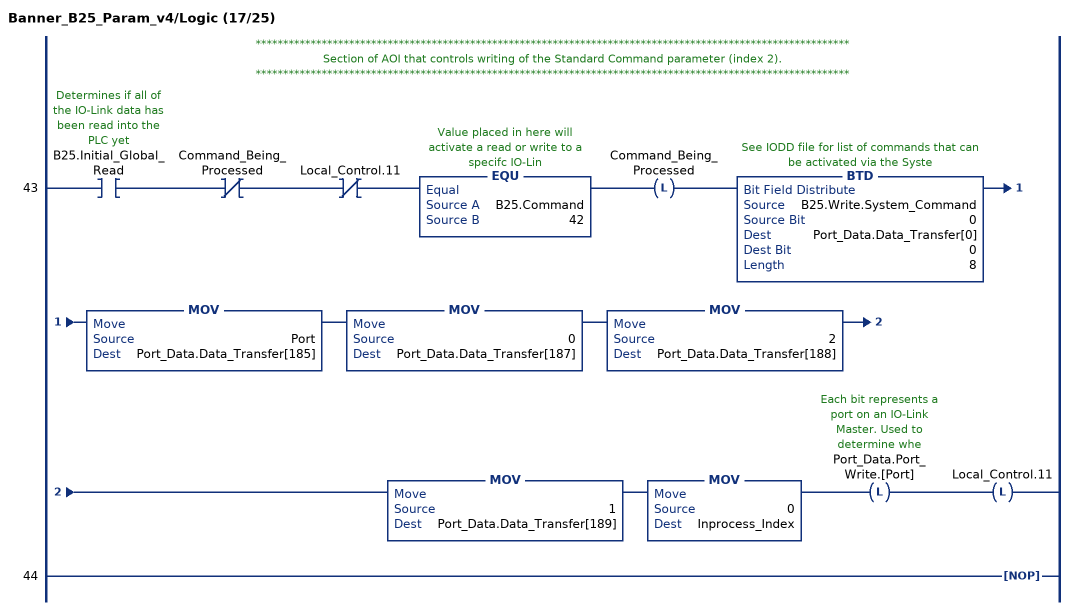
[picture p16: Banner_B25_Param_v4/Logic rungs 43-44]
   // ************************************************************************************************************
   // Section of AOI that controls writing of the Standard Command parameter (index 2).
   // ************************************************************************************************************
   43: XIC(B25.Initial_Global_Read)XIO(Command_Being_Processed)XIO(Local_Control.11)EQU(B25.Command,42)OTL(Command_Being_Processed)BTD(B25.Write.System_Command,0,Port_Data.Data_Transfer[0],0,8)MOV(Port,Port_Data.Data_Transfer[185])MOV(0,Port_Data.Data_Transfer[187])MOV(2,Port_Data.Data_Transfer[188])MOV(1,Port_Data.Data_Transfer[189])MOV(0,Inprocess_Index)OTL(Port_Data.Port_Write.[Port])OTL(Local_Control.11);
   44: NOP();
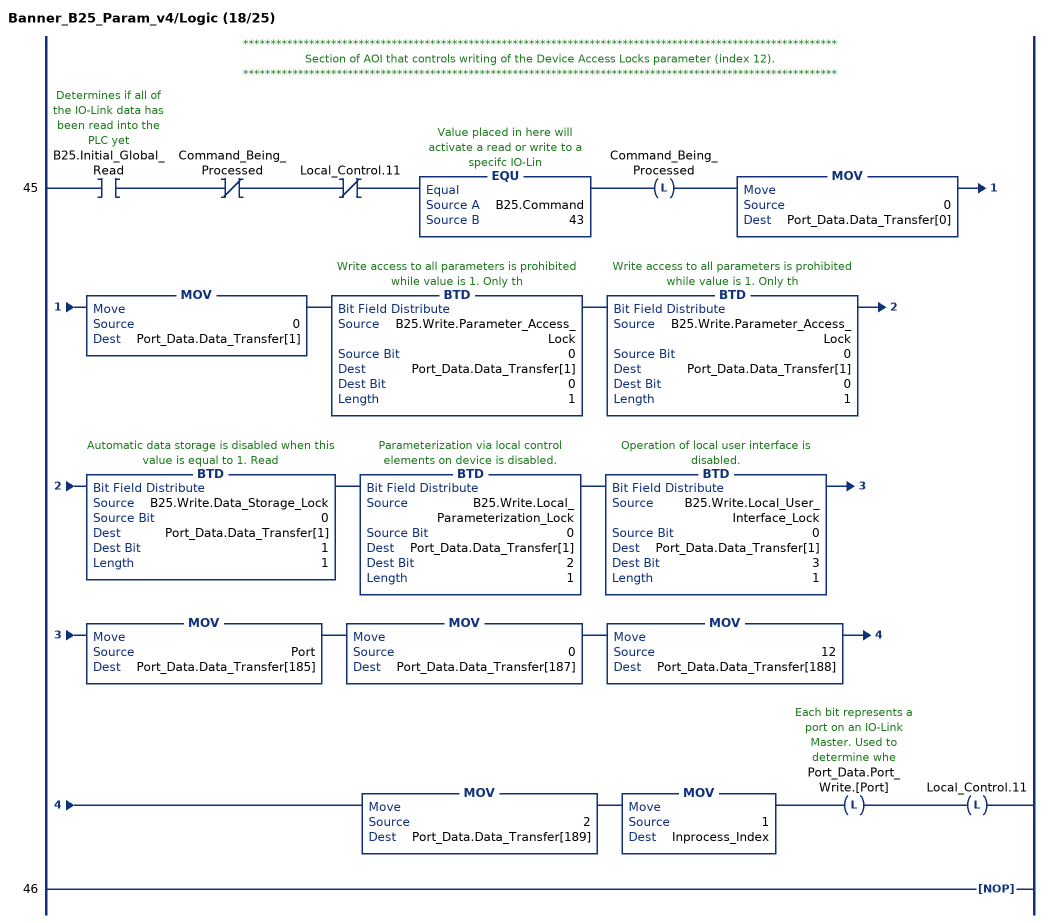
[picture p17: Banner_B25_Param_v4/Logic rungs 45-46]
   // ************************************************************************************************************
   // Section of AOI that controls writing of the Device Access Locks parameter (index 12).
   // ************************************************************************************************************
   45: XIC(B25.Initial_Global_Read)XIO(Command_Being_Processed)XIO(Local_Control.11)EQU(B25.Command,43)OTL(Command_Being_Processed)MOV(0,Port_Data.Data_Transfer[0])MOV(0,Port_Data.Data_Transfer[1])BTD(B25.Write.Parameter_Access_Lock,0,Port_Data.Data_Transfer[1],0,1)BTD(B25.Write.Parameter_Access_Lock,0,Port_Data.Data_Transfer[1],0,1)BTD(B25.Write.Data_Storage_Lock,0,Port_Data.Data_Transfer[1],1,1)BTD(B25.Write.Local_Parameterization_Lock,0,Port_Data.Data_Transfer[1],2,1)BTD(B25.Write.Local_User_Interface_Lock,0,Port_Data.Data_Transfer[1],3,1)MOV(Port,Port_Data.Data_Transfer[185])MOV(0,Port_Data.Data_Transfer[187])MOV(12,Port_Data.Data_Transfer[188])MOV(2,Port_Data.Data_Transfer[189])MOV(1,Inprocess_Index)OTL(Port_Data.Port_Write.[Port])OTL(Local_Control.11);
   46: NOP();
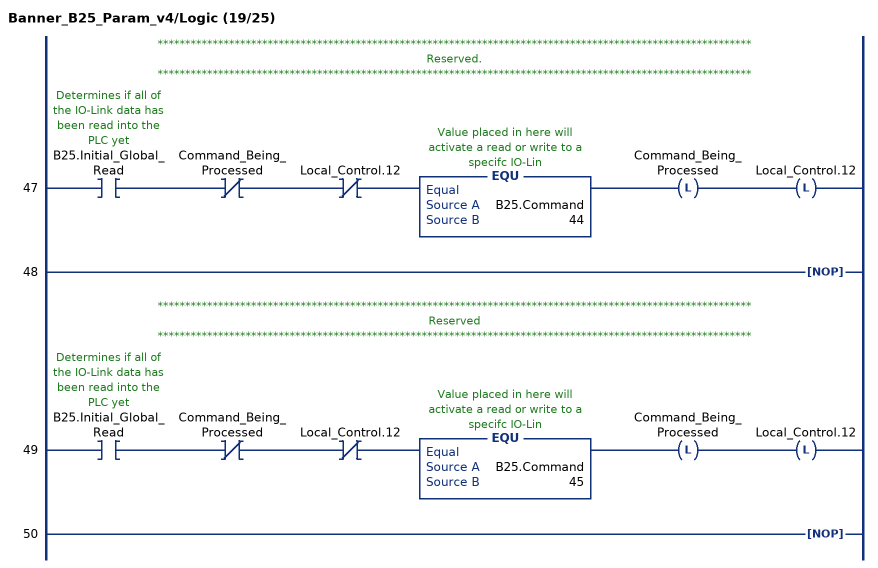
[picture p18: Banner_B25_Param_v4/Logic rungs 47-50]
   // ************************************************************************************************************
   // Reserved.
   // ************************************************************************************************************
   47: XIC(B25.Initial_Global_Read)XIO(Command_Being_Processed)XIO(Local_Control.12)EQU(B25.Command,44)OTL(Command_Being_Processed)OTL(Local_Control.12);
   48: NOP();
   // ************************************************************************************************************
   // Reserved
   // ************************************************************************************************************
   49: XIC(B25.Initial_Global_Read)XIO(Command_Being_Processed)XIO(Local_Control.12)EQU(B25.Command,45)OTL(Command_Being_Processed)OTL(Local_Control.12);
   50: NOP();
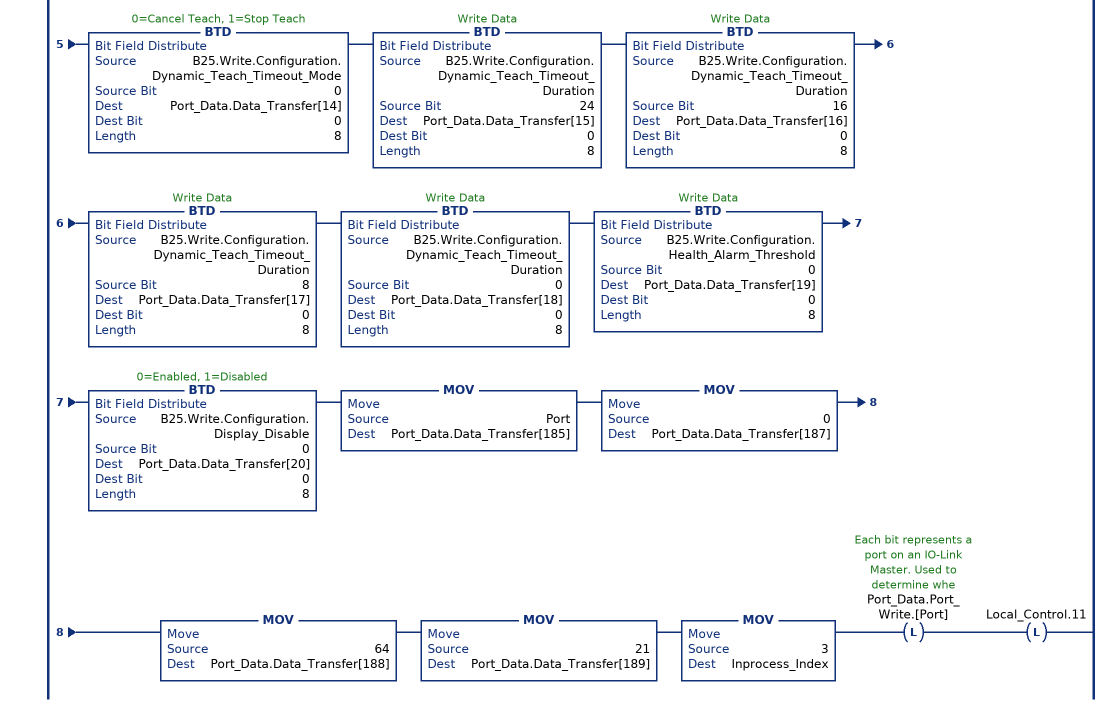
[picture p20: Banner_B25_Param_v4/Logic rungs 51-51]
   // ************************************************************************************************************
   // Section of AOI that controls writing of the Configuration parameter (index 64).
   // ************************************************************************************************************
   51: XIC(B25.Initial_Global_Read)XIO(Command_Being_Processed)XIO(Local_Control.11)EQU(B25.Command,46)OTL(Command_Being_Processed)BTD(B25.Write.Configuration.Sensor_Lockout,0,Port_Data.Data_Transfer[0],0,8)BTD(B25.Write.Configuration.Sensitivity,0,Port_Data.Data_Transfer[1],0,8)BTD(B25.Write.Configuration.Pin2_Function,0,Port_Data.Data_Transfer[2],0,8)BTD(B25.Write.Configuration.Pin2_Pin4_Polarity,0,Port_Data.Data_Transfer[3],0,8)BTD(B25.Write.Configuration.Output_Logic,0,Port_Data.Data_Transfer[4],0,8)BTD(B25.Write.Configuration.Output_Delay_Mode,0,Port_Data.Data_Transfer[5],0,8)BTD(B25.Write.Configuration.Output_On_Delay,24,Port_Data.Data_Transfer[6],0,8)BTD(B25.Write.Configuration.Output_On_Delay,16,Port_Data.Data_Transfer[7],0,8)BTD(B25.Write.Configuration.Output_On_Delay,8,Port_Data.Data_Transfer[8],0,8)BTD(B25.Write.Configuration.Output_On_Delay,0,Port_Data.Data_Transfer[9],0,8)BTD(B25.Write.Configuration.Output_Off_Delay,24,Port_Data.Data_Transfer[10],0,8)BTD(B25.Write.Configuration.Output_Off_Delay,16,Port_Data.Data_Transfer[11],0,8)BTD(B25.Write.Configuration.Output_Off_Delay,8,Port_Data.Data_Transfer[12],0,8)BTD(B25.Write.Configuration.Output_Off_Delay,0,Port_Data.Data_Transfer[13],0,8)BTD(B25.Write.Configuration.Dynamic_Teach_Timeout_Mode,0,Port_Data.Data_Transfer[14],0,8)BTD(B25.Write.Configuration.Dynamic_Teach_Timeout_Duration,24,Port_Data.Data_Transfer[15],0,8)BTD(B25.Write.Configuration.Dynamic_Teach_Timeout_Duration,16,Port_Data.Data_Transfer[16],0,8)BTD(B25.Write.Configuration.Dynamic_Teach_Timeout_Duration,8,Port_Data.Data_Transfer[17],0,8)BTD(B25.Write.Configuration.Dynamic_Teach_Timeout_Duration,0,Port_Data.Data_Transfer[18],0,8)BTD(B25.Write.Configuration.Health_Alarm_Threshold,0,Port_Data.Data_Transfer[19],0,8)BTD(B25.Write.Configuration.Display_Disable,0,Port_Data.Data_Transfer[20],0,8)MOV(Port,Port_Data.Data_Transfer[185])MOV(0,Port_Data.Data_Transfer[187])MOV(64,Port_Data.Data_Transfer[188])MOV(21,Port_Data.Data_Transfer[189])MOV(3,Inprocess_Index)OTL(Port_Data.Port_Write.[Port])OTL(Local_Control.11);
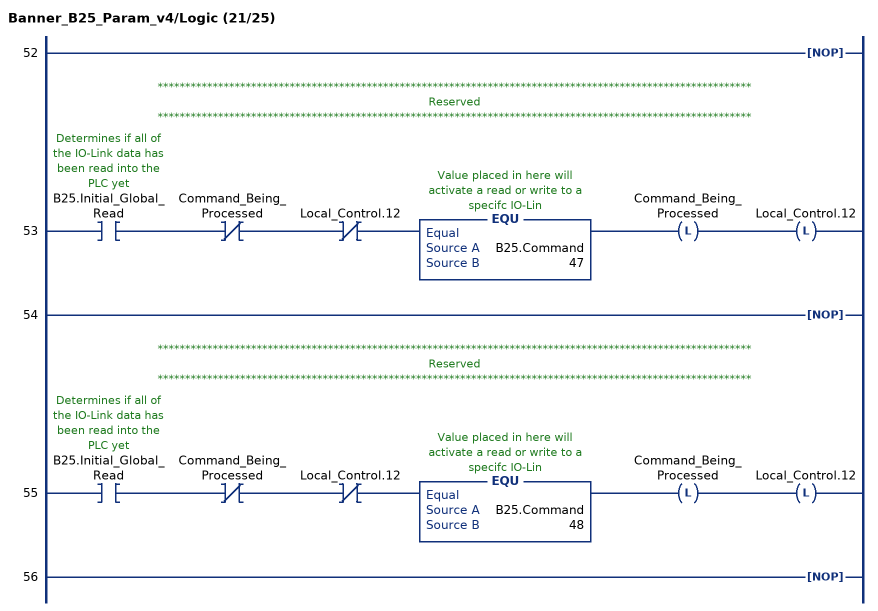
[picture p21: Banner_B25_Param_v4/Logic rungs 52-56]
   52: NOP();
   // ************************************************************************************************************
   // Reserved
   // ************************************************************************************************************
   53: XIC(B25.Initial_Global_Read)XIO(Command_Being_Processed)XIO(Local_Control.12)EQU(B25.Command,47)OTL(Command_Being_Processed)OTL(Local_Control.12);
   54: NOP();
   // ************************************************************************************************************
   // Reserved
   // ************************************************************************************************************
   55: XIC(B25.Initial_Global_Read)XIO(Command_Being_Processed)XIO(Local_Control.12)EQU(B25.Command,48)OTL(Command_Being_Processed)OTL(Local_Control.12);
   56: NOP();
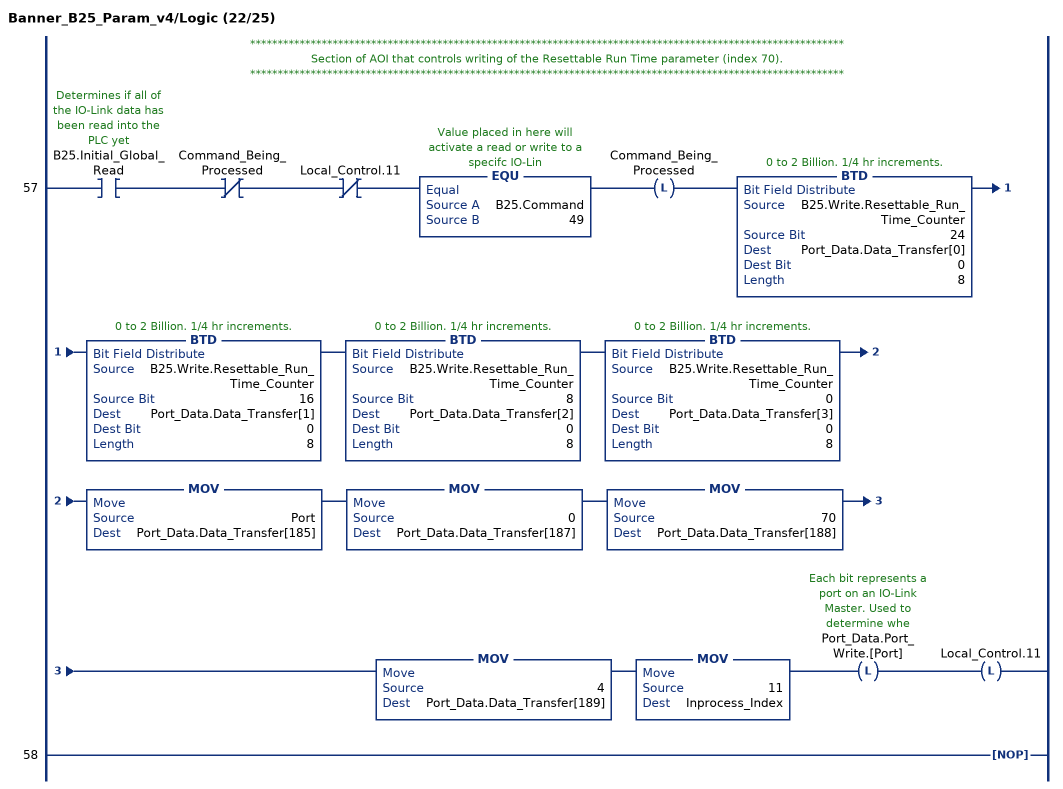
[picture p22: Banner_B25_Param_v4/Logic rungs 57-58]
   // ************************************************************************************************************
   // Section of AOI that controls writing of the Resettable Run Time parameter (index 70).
   // ************************************************************************************************************
   57: XIC(B25.Initial_Global_Read)XIO(Command_Being_Processed)XIO(Local_Control.11)EQU(B25.Command,49)OTL(Command_Being_Processed)BTD(B25.Write.Resettable_Run_Time_Counter,24,Port_Data.Data_Transfer[0],0,8)BTD(B25.Write.Resettable_Run_Time_Counter,16,Port_Data.Data_Transfer[1],0,8)BTD(B25.Write.Resettable_Run_Time_Counter,8,Port_Data.Data_Transfer[2],0,8)BTD(B25.Write.Resettable_Run_Time_Counter,0,Port_Data.Data_Transfer[3],0,8)MOV(Port,Port_Data.Data_Transfer[185])MOV(0,Port_Data.Data_Transfer[187])MOV(70,Port_Data.Data_Transfer[188])MOV(4,Port_Data.Data_Transfer[189])MOV(11,Inprocess_Index)OTL(Port_Data.Port_Write.[Port])OTL(Local_Control.11);
   58: NOP();
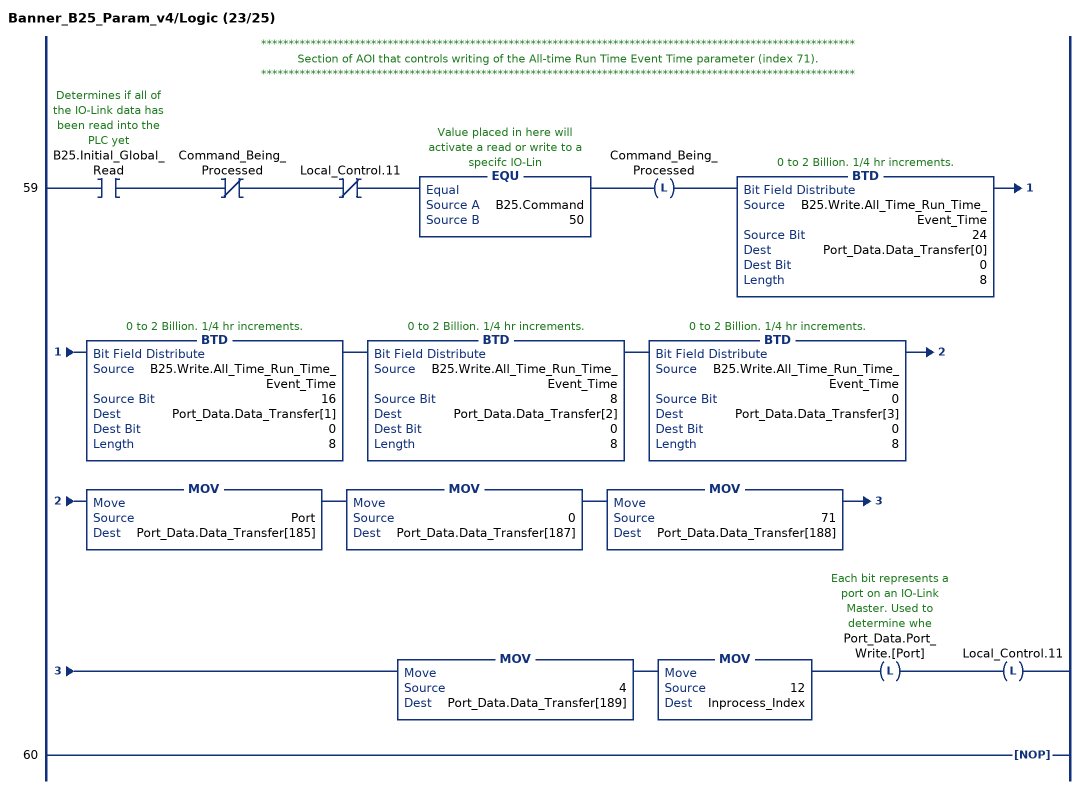
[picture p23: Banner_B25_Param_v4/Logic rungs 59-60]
   // ************************************************************************************************************
   // Section of AOI that controls writing of the All-time Run Time Event Time parameter (index 71).
   // ************************************************************************************************************
   59: XIC(B25.Initial_Global_Read)XIO(Command_Being_Processed)XIO(Local_Control.11)EQU(B25.Command,50)OTL(Command_Being_Processed)BTD(B25.Write.All_Time_Run_Time_Event_Time,24,Port_Data.Data_Transfer[0],0,8)BTD(B25.Write.All_Time_Run_Time_Event_Time,16,Port_Data.Data_Transfer[1],0,8)BTD(B25.Write.All_Time_Run_Time_Event_Time,8,Port_Data.Data_Transfer[2],0,8)BTD(B25.Write.All_Time_Run_Time_Event_Time,0,Port_Data.Data_Transfer[3],0,8)MOV(Port,Port_Data.Data_Transfer[185])MOV(0,Port_Data.Data_Transfer[187])MOV(71,Port_Data.Data_Transfer[188])MOV(4,Port_Data.Data_Transfer[189])MOV(12,Inprocess_Index)OTL(Port_Data.Port_Write.[Port])OTL(Local_Control.11);
   60: NOP();
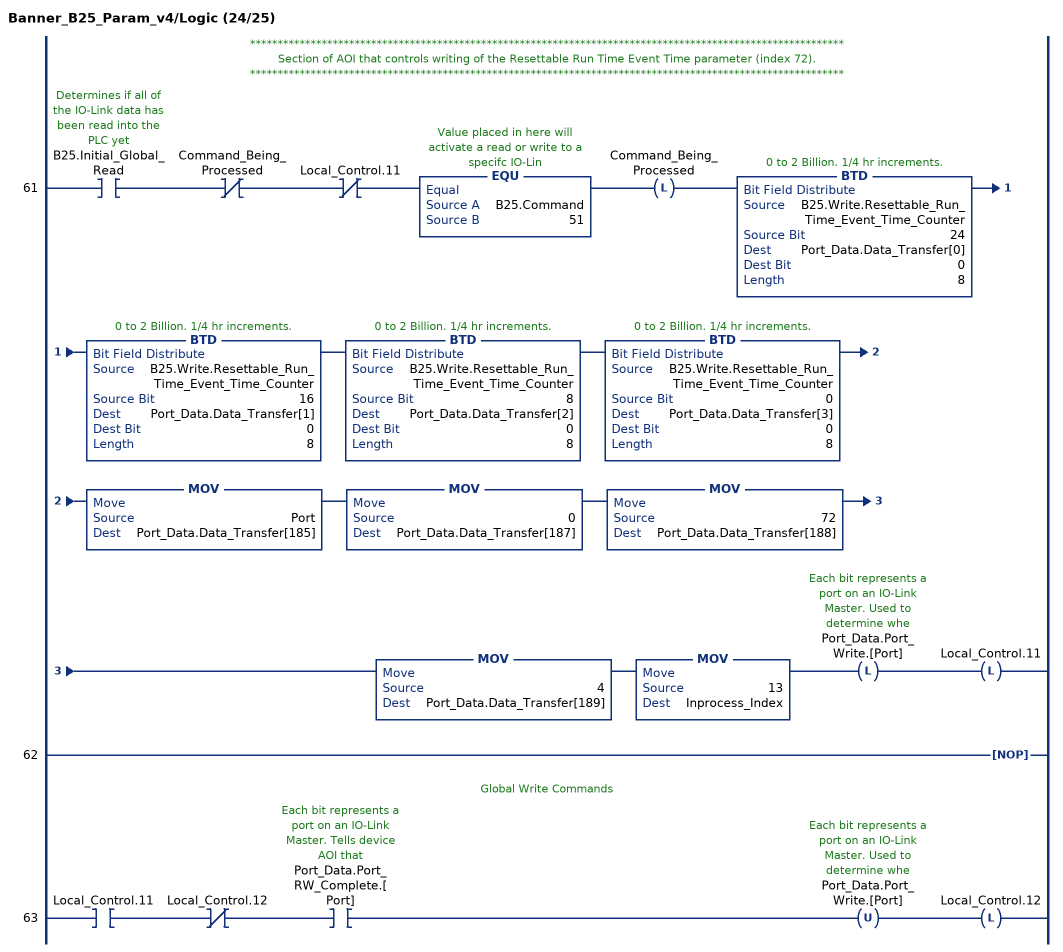
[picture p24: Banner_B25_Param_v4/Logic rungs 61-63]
   // ************************************************************************************************************
   // Section of AOI that controls writing of the Resettable Run Time Event Time parameter (index 72).
   // ************************************************************************************************************
   61: XIC(B25.Initial_Global_Read)XIO(Command_Being_Processed)XIO(Local_Control.11)EQU(B25.Command,51)OTL(Command_Being_Processed)BTD(B25.Write.Resettable_Run_Time_Event_Time_Counter,24,Port_Data.Data_Transfer[0],0,8)BTD(B25.Write.Resettable_Run_Time_Event_Time_Counter,16,Port_Data.Data_Transfer[1],0,8)BTD(B25.Write.Resettable_Run_Time_Event_Time_Counter,8,Port_Data.Data_Transfer[2],0,8)BTD(B25.Write.Resettable_Run_Time_Event_Time_Counter,0,Port_Data.Data_Transfer[3],0,8)MOV(Port,Port_Data.Data_Transfer[185])MOV(0,Port_Data.Data_Transfer[187])MOV(72,Port_Data.Data_Transfer[188])MOV(4,Port_Data.Data_Transfer[189])MOV(13,Inprocess_Index)OTL(Port_Data.Port_Write.[Port])OTL(Local_Control.11);
   62: NOP();
   // Global Write Commands
   63: XIC(Local_Control.11)XIO(Local_Control.12)XIC(Port_Data.Port_RW_Complete.[Port])OTU(Port_Data.Port_Write.[Port])OTL(Local_Control.12);
